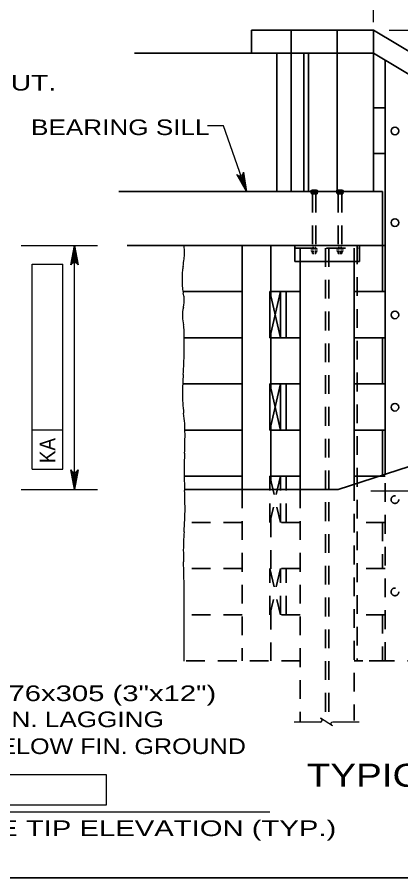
# Model space of a CAD drawing. Extents: x -6.4 to 73.1, y -66 to 0.
# Drawn here: x 48 to 50.94, y -21.25 to -14.64 of the extents above; entities that cross this region are included whole.
import ezdxf
from ezdxf.enums import TextEntityAlignment as Align

# ---------------------------------------------------------------- set-up
doc = ezdxf.new("R2010")
doc.units = 0
doc.header["$LTSCALE"] = 0.048
doc.header["$PDMODE"] = 32
doc.header["$PDSIZE"] = 0.024
doc.linetypes.add('MEDIUM_DASHED', pattern=[4.5, 3, -1.5])
for name, color, linetype, lineweight in [('1', 7, 'Continuous', 13), ('3', 7, 'Continuous', 35), ('4', 7, 'Continuous', 25), ('5', 7, 'Continuous', 25), ('8', 7, 'Continuous', 25)]:
    doc.layers.add(name, color=color, linetype=linetype, lineweight=lineweight)

msp = doc.modelspace()

# ---------------------------------------------------------------- hatches: boundary and pattern name
at = {"layer": '4'}
for points in [[(49.75758, -15.98183), (49.72792, -15.86708), (49.70933, -15.87358)], [(48.41525, -16.51333), (48.45467, -16.51333), (48.435, -16.39525)], [(48.41525, -18.14983), (48.45467, -18.14983), (48.435, -18.268)]]:
    msp.add_hatch(color=256, dxfattribs=at).paths.add_polyline_path(points)

# ---------------------------------------------------------------- linework, layer by layer
at = {"layer": '1', "lineweight": 35}
msp.add_lwpolyline([(35.75, -21.25), (67.25, -21.25), (67.25, -0.75), (35.75, -0.75)], close=True, dxfattribs=at)
at = {"layer": '3'}
for p, q in [((49.79517, -14.74175), (50.73183, -14.74175)), ((49.79517, -14.74175), (49.79517, -14.91892)), ((50.10025, -14.74175), (50.10025, -15.98183)), ((50.4525, -14.74175), (50.4525, -14.91892)), ((50.73183, -14.74175), (54.24875, -16.83867)), ((50.73183, -14.74175), (50.73183, -14.91892)), ((48.896, -14.91892), (50.73183, -14.91892)), ((49.99017, -14.91892), (49.99017, -15.98183)), ((50.1985, -14.91892), (50.1985, -15.98183)), ((50.23233, -14.91892), (50.23233, -15.98183)), ((50.4525, -14.91892), (50.4525, -15.98183)), ((50.73183, -14.91892), (54.24875, -17.01583)), ((50.73183, -14.91892), (50.73183, -15.98183)), ((50.8215, -18.15183), (50.8215, -14.97242)), ((50.8215, -15.33775), (50.73183, -15.33775)), ((50.8215, -15.68933), (50.73183, -15.68933)), ((48.77725, -15.98183), (50.80075, -15.98183)), ((50.25625, -15.99775), (50.25625, -15.98558)), ((50.294, -15.98183), (50.26158, -15.98183)), ((50.26733, -15.98558), (50.26733, -15.99775)), ((50.28867, -15.98558), (50.28867, -15.99775)), ((50.45408, -15.99775), (50.45408, -15.98558)), ((50.45908, -15.98183), (50.49142, -15.98183)), ((50.46442, -15.98558), (50.46442, -15.99775)), ((50.48575, -15.98558), (50.48575, -15.99775)), ((50.49675, -15.99775), (50.49675, -15.98558)), ((50.80075, -15.98183), (50.80075, -16.74958)), ((50.49675, -15.99775), (50.45408, -15.99775)), ((48.8395, -16.39525), (50.8215, -16.39525)), ((49.72392, -16.39525), (49.72392, -18.268)), ((49.944, -16.39525), (49.944, -16.78)), ((50.12892, -16.39525), (50.12892, -16.51825)), ((50.25583, -16.42667), (50.25583, -16.42133)), ((50.25583, -16.43967), (50.25583, -16.43342)), ((50.29358, -16.41758), (50.26117, -16.41758)), ((50.27225, -16.44342), (50.26117, -16.44342)), ((50.27333, -16.41033), (50.26442, -16.41033)), ((50.26442, -16.44342), (50.26442, -16.45625)), ((50.26692, -16.42133), (50.26692, -16.42667)), ((50.26692, -16.43342), (50.26692, -16.43967)), ((50.29067, -16.41033), (50.28233, -16.41033)), ((50.29358, -16.44342), (50.28275, -16.44342)), ((50.28825, -16.42133), (50.28825, -16.42667)), ((50.28825, -16.43342), (50.28825, -16.43967)), ((50.29067, -16.44342), (50.29067, -16.45625)), ((50.2985, -16.42667), (50.2985, -16.42133)), ((50.2985, -16.43967), (50.2985, -16.43342)), ((50.45442, -16.42725), (50.45442, -16.42133)), ((50.45442, -16.43967), (50.45442, -16.43333)), ((50.45942, -16.41758), (50.49175, -16.41758)), ((50.45942, -16.44342), (50.47175, -16.44342)), ((50.46225, -16.41033), (50.47175, -16.41033)), ((50.46225, -16.44342), (50.46225, -16.45625)), ((50.46475, -16.42133), (50.46475, -16.42725)), ((50.46475, -16.43333), (50.46475, -16.43967)), ((50.47775, -16.44342), (50.49175, -16.44342)), ((50.47892, -16.41033), (50.4885, -16.41033)), ((50.48608, -16.42133), (50.48608, -16.42725)), ((50.48608, -16.43333), (50.48608, -16.43967)), ((50.4885, -16.44342), (50.4885, -16.45625)), ((50.49708, -16.42725), (50.49708, -16.42133)), ((50.49708, -16.43967), (50.49708, -16.43333)), ((50.62408, -16.39525), (50.62408, -16.51825)), ((50.27392, -16.45625), (50.26442, -16.45625)), ((50.29067, -16.45625), (50.28117, -16.45625)), ((50.46225, -16.45625), (50.47175, -16.45625)), ((50.47775, -16.45625), (50.4885, -16.45625)), ((50.12892, -16.51825), (50.62408, -16.51825)), ((50.16992, -16.51825), (50.16992, -18.268)), ((50.58308, -16.51825), (50.58308, -18.21183)), ((49.72392, -16.74958), (49.26917, -16.74958)), ((49.93717, -17.10392), (49.93717, -16.74958)), ((49.93717, -16.74958), (50.01742, -17.10392)), ((50.01742, -16.74958), (49.93717, -17.10392)), ((50.16992, -16.74958), (49.93717, -16.74958)), ((50.01742, -17.10392), (50.01742, -16.74958)), ((50.06283, -17.10392), (50.06283, -16.74958)), ((50.16992, -16.74958), (50.12667, -16.74958)), ((50.8215, -16.74958), (50.58308, -16.74958)), ((49.72392, -17.10392), (49.27925, -17.10392)), ((50.16992, -17.10392), (49.93717, -17.10392)), ((49.944, -17.0735), (49.944, -17.48867)), ((54.09275, -17.09908), (50.46075, -18.268)), ((50.8215, -17.10392), (50.58308, -17.10392)), ((50.80075, -17.10392), (50.80075, -17.45825)), ((49.72392, -17.45825), (49.26717, -17.45825)), ((49.93717, -17.81258), (49.93717, -17.45825)), ((49.93717, -17.45825), (50.01742, -17.81258)), ((50.16992, -17.45825), (49.93717, -17.45825)), ((50.06283, -17.81258), (50.06283, -17.45825)), ((50.8215, -17.45825), (50.58308, -17.45825)), ((49.72392, -17.81258), (49.28442, -17.81258)), ((50.16992, -17.81258), (49.93717, -17.81258)), ((49.944, -17.78217), (49.944, -18.19733)), ((50.8215, -17.81258), (50.58308, -17.81258)), ((50.80075, -17.81258), (50.80075, -18.16692)), ((49.72392, -18.16692), (49.27875, -18.16692)), ((50.16992, -18.16692), (49.93717, -18.16692)), ((50.8215, -18.16692), (50.58308, -18.16692)), ((49.2815, -18.268), (50.46075, -18.268))]:
    msp.add_line(p, q, dxfattribs=at)
at = {"layer": '3', "linetype": 'MEDIUM_DASHED'}
for p, q in [((50.2645, -15.99775), (50.2645, -16.41758)), ((50.29075, -15.99775), (50.29075, -16.41758)), ((50.46233, -15.99775), (50.46233, -16.41758)), ((50.48858, -15.99775), (50.48858, -16.41758)), ((50.6075, -16.39525), (50.6075, -19.58425)), ((49.93717, -18.52125), (49.93717, -18.16692)), ((49.93717, -18.16692), (50.01742, -18.52125)), ((50.06283, -18.52125), (50.06283, -18.16692)), ((50.8215, -19.58425), (50.8215, -18.15183)), ((50.58308, -18.21183), (50.58308, -20.0425)), ((49.72392, -18.268), (49.72392, -19.58425)), ((50.16992, -18.268), (50.16992, -20.05342)), ((49.944, -18.49083), (49.944, -18.906)), ((49.72392, -18.52125), (49.28225, -18.52125)), ((50.16992, -18.52125), (49.93717, -18.52125)), ((50.8215, -18.52125), (50.58308, -18.52125)), ((50.80075, -18.52125), (50.80075, -18.87558)), ((49.72392, -18.87558), (49.27475, -18.87558)), ((49.93717, -19.22992), (49.93717, -18.87558)), ((49.93717, -18.87558), (50.01742, -19.22992)), ((50.01742, -18.87558), (49.93717, -19.22992)), ((50.16992, -18.87558), (49.93717, -18.87558)), ((50.01742, -19.22992), (50.01742, -18.87558)), ((50.06283, -19.22992), (50.06283, -18.87558)), ((50.8215, -18.87558), (50.58308, -18.87558)), ((49.944, -19.1995), (49.944, -19.58425)), ((49.72392, -19.22992), (49.27842, -19.22992)), ((50.16992, -19.22992), (49.93717, -19.22992)), ((50.8215, -19.22992), (50.58308, -19.22992)), ((50.80075, -19.22992), (50.80075, -19.58425)), ((50.16992, -19.58425), (49.27842, -19.58425)), ((51.87083, -19.58425), (50.58308, -19.58425)), ((50.69825, -19.58425), (50.87542, -19.58425))]:
    msp.add_line(p, q, dxfattribs=at)
at = {"layer": '3'}
for points in [[(50.25625, -15.99775), (50.29892, -15.99775), (50.29892, -15.98558)], [(50.01742, -17.81258), (50.01742, -17.45825), (49.93717, -17.81258)]]:
    msp.add_lwpolyline(points, dxfattribs=at)
at = {"layer": '3', "linetype": 'MEDIUM_DASHED'}
msp.add_lwpolyline([(50.01742, -18.52125), (50.01742, -18.16692), (49.93717, -18.52125)], dxfattribs=at)
at = {"layer": '3'}
for centre in [(50.89713, -15.51643), (50.89713, -16.22006), (50.89713, -16.92872), (50.89713, -17.63738)]:
    msp.add_circle(centre, 0.02953, dxfattribs=at)
at = {"layer": '3', "linetype": 'MEDIUM_DASHED'}
for centre in [(50.89713, -18.34604), (50.89713, -19.0547)]:
    msp.add_circle(centre, 0.02953, dxfattribs=at)
at = {"layer": '3'}
for centre, radius, start, end in [((50.26177, -15.98774), 0.00592, 88.17294, 158.71305), ((50.26177, -15.98774), 0.00592, 21.28694, 88.17294), ((50.27795, -15.99878), 0.01696, 51.05, 128.95), ((50.29375, -15.9872), 0.00539, 17.45181, 162.54819), ((50.45923, -15.9872), 0.00539, 17.45181, 162.54819), ((50.47503, -15.99878), 0.01696, 51.05, 128.95), ((50.49122, -15.98774), 0.00592, 91.82706, 158.71306), ((50.49122, -15.98774), 0.00592, 21.28694, 91.82706), ((50.2614, -16.42351), 0.00592, 88.17294, 158.71305), ((50.2614, -16.4375), 0.00592, 201.28694, 271.82706), ((50.2614, -16.42351), 0.00592, 21.28694, 88.17294), ((50.2614, -16.4375), 0.00592, 271.82706, 338.71306), ((50.27758, -16.43455), 0.01696, 51.05, 128.95), ((50.27758, -16.42646), 0.01696, 231.05, 256.0077), ((50.27758, -16.42646), 0.01696, 284.34274, 308.95), ((50.29339, -16.42298), 0.00539, 17.45181, 162.54819), ((50.29339, -16.43803), 0.00539, 197.45181, 342.54819), ((50.45962, -16.42298), 0.00539, 17.45181, 162.54819), ((50.45962, -16.43803), 0.00539, 197.45181, 342.54819), ((50.47542, -16.43455), 0.01696, 51.05, 128.95), ((50.47542, -16.42646), 0.01696, 231.05, 257.49177), ((50.47542, -16.42646), 0.01696, 277.88621, 308.95), ((50.4916, -16.42351), 0.00592, 91.82706, 158.71306), ((50.4916, -16.4375), 0.00592, 201.28694, 268.17294), ((50.4916, -16.42351), 0.00592, 21.28694, 91.82706), ((50.4916, -16.4375), 0.00592, 268.17294, 338.71305)]:
    msp.add_arc(centre, radius, start, end, dxfattribs=at)
at = {"layer": '3', "lineweight": 25}
for centre, radius, start, end in [((48.42474, -16.45944), 0.85604, 0, 4.30041), ((47.96951, -16.33175), 1.31933, 350.22511, 352.77729), ((48.97705, -16.45944), 0.30373, 352.77729, 0), ((49.6657, -16.62397), 0.40185, 170.22511, 174.85038), ((49.9781, -16.65213), 0.71552, 174.85038, 180), ((50.14143, -16.65213), 0.87884, 180, 184.64624), ((49.4982, -16.7044), 0.2335, 184.64624, 194.09577), ((49.02709, -16.8227), 0.25224, 5.00495, 14.09577), ((49.07832, -16.81821), 0.20082, 345.34471, 5.00496), ((49.49811, -16.92799), 0.23309, 165.34471, 183.58075), ((49.76231, -16.91146), 0.4978, 183.58075, 190.71943), ((48.975, -17.0605), 0.30349, 1.57285, 10.71943), ((47.04107, -17.1136), 2.23815, 0, 1.57285), ((42.58886, -17.1136), 6.69035, 359.0903, 0), ((46.28593, -17.17231), 2.99281, 355.92772, 359.0903), ((51.55928, -17.54774), 2.29388, 175.92772, 179.54026), ((50.40898, -17.53851), 1.14355, 179.54026, 187.19626), ((47.96778, -17.84675), 1.31704, 0.06302, 7.19626), ((46.30843, -17.84857), 2.97639, 357.26093, 0.06302), ((51.96358, -18.11912), 2.68522, 177.26093, 180.21106), ((52.99667, -18.11532), 3.71833, 180.21106, 182.50023), ((46.20283, -18.41197), 3.08199, 359.98578, 2.50023), ((47.00966, -18.41217), 2.27516, 355.43722, 359.98579), ((51.09012, -18.73781), 1.81827, 175.43722, 180.5256), ((52.82053, -18.72194), 3.54876, 180.5256, 181.65618), ((20.08141, -19.66855), 29.20404, 1.26207, 1.65618), ((46.29577, -19.09102), 2.98333, 0, 1.26207), ((-119.97358, -19.09102), 169.25267, 359.83244, 0)]:
    msp.add_arc(centre, radius, start, end, dxfattribs=at)
at = {"layer": '3'}
for p in [(50.26342, -15.982), (50.264, -15.982), (50.26467, -15.982), (50.26492, -15.98258), (50.26525, -15.982), (50.2655, -15.98258), (50.26583, -15.982), (50.26583, -15.98317), (50.26608, -15.98258), (50.26642, -15.982), (50.26642, -15.98317), (50.26667, -15.98258), (50.26675, -15.98375), (50.267, -15.982), (50.267, -15.98317), (50.267, -15.98433), (50.26725, -15.98258), (50.26725, -15.98375), (50.26725, -15.98492), (50.26758, -15.982), (50.26758, -15.98317), (50.26758, -15.98433), (50.26792, -15.98258), (50.26792, -15.98375), (50.26792, -15.98492), (50.26817, -15.982), (50.26817, -15.98317), (50.26817, -15.98433), (50.2685, -15.98258), (50.2685, -15.98375), (50.26875, -15.982), (50.26875, -15.98317), (50.26875, -15.98433), (50.26908, -15.98258), (50.26908, -15.98375), (50.26933, -15.982), (50.26933, -15.98317), (50.26967, -15.98258), (50.26967, -15.98375), (50.26992, -15.982), (50.26992, -15.98317), (50.27025, -15.98258), (50.2705, -15.982), (50.2705, -15.98317), (50.27083, -15.98258), (50.27108, -15.982), (50.27108, -15.98317), (50.27142, -15.98258), (50.27175, -15.982), (50.272, -15.98258), (50.27233, -15.982), (50.27258, -15.98258), (50.27292, -15.982), (50.2735, -15.982), (50.27408, -15.982), (50.27467, -15.982), (50.27525, -15.982), (50.28058, -15.982), (50.28117, -15.982), (50.28175, -15.982), (50.28233, -15.982), (50.28292, -15.982), (50.28325, -15.98258), (50.2835, -15.982), (50.28383, -15.98258), (50.28417, -15.982), (50.28442, -15.98258), (50.28467, -15.982), (50.28467, -15.98317), (50.285, -15.98258), (50.28533, -15.982), (50.28533, -15.98317), (50.28558, -15.98258), (50.28592, -15.982), (50.28592, -15.98317), (50.28617, -15.98258), (50.28617, -15.98375), (50.2865, -15.982), (50.2865, -15.98317), (50.28675, -15.98258), (50.28675, -15.98375), (50.28708, -15.982), (50.28708, -15.98317), (50.28708, -15.98433), (50.28733, -15.98258), (50.28733, -15.98375), (50.28767, -15.982), (50.28767, -15.98317), (50.28767, -15.98433), (50.28792, -15.98258), (50.28792, -15.98375), (50.28792, -15.98492), (50.28825, -15.982), (50.28825, -15.98317), (50.28825, -15.98433), (50.2885, -15.98258), (50.2885, -15.98375), (50.2885, -15.98492), (50.28867, -15.98258), (50.28867, -15.98375), (50.28867, -15.98492), (50.28892, -15.982), (50.28892, -15.98317), (50.28892, -15.98433), (50.28925, -15.98258), (50.28925, -15.98375), (50.2895, -15.982), (50.2895, -15.98317), (50.28983, -15.98258), (50.29017, -15.982), (50.29017, -15.98317), (50.29042, -15.98258), (50.29067, -15.982), (50.291, -15.98258), (50.29133, -15.982), (50.29192, -15.982), (50.2925, -15.982), (50.4605, -15.982), (50.46108, -15.982), (50.46175, -15.982), (50.462, -15.98258), (50.46233, -15.982), (50.46258, -15.98258), (50.46292, -15.982), (50.46292, -15.98317), (50.46317, -15.98258), (50.4635, -15.982), (50.4635, -15.98317), (50.46375, -15.98258), (50.46383, -15.98375), (50.46408, -15.982), (50.46408, -15.98317), (50.46408, -15.98433), (50.46433, -15.98258), (50.46433, -15.98375), (50.46433, -15.98492), (50.4645, -15.98258), (50.4645, -15.98375), (50.4645, -15.98492), (50.46475, -15.982), (50.46475, -15.98317), (50.46475, -15.98433), (50.46508, -15.98258), (50.46508, -15.98375), (50.46508, -15.98492), (50.46533, -15.982), (50.46533, -15.98317), (50.46533, -15.98433), (50.46567, -15.98258), (50.46567, -15.98375), (50.46592, -15.982), (50.46592, -15.98317), (50.46592, -15.98433), (50.46625, -15.98258), (50.46625, -15.98375), (50.4665, -15.982), (50.4665, -15.98317), (50.46683, -15.98258), (50.46683, -15.98375), (50.46708, -15.982), (50.46708, -15.98317), (50.46742, -15.98258), (50.46775, -15.982), (50.46775, -15.98317), (50.468, -15.98258), (50.46833, -15.982), (50.46833, -15.98317), (50.46858, -15.98258), (50.46892, -15.982), (50.46917, -15.98258), (50.4695, -15.982), (50.46983, -15.98258), (50.47008, -15.982), (50.47067, -15.982), (50.47125, -15.982), (50.47183, -15.982), (50.47242, -15.982), (50.47775, -15.982), (50.47833, -15.982), (50.47892, -15.982), (50.4795, -15.982), (50.48017, -15.982), (50.48042, -15.98258), (50.48067, -15.982), (50.481, -15.98258), (50.48133, -15.982), (50.48158, -15.98258), (50.48192, -15.982), (50.48192, -15.98317), (50.48217, -15.98258), (50.4825, -15.982), (50.4825, -15.98317), (50.48275, -15.98258), (50.48308, -15.982), (50.48308, -15.98317), (50.48333, -15.98258), (50.48333, -15.98375), (50.48367, -15.982), (50.48367, -15.98317), (50.484, -15.98258), (50.484, -15.98375), (50.48425, -15.982), (50.48425, -15.98317), (50.48425, -15.98433), (50.4845, -15.98258), (50.4845, -15.98375), (50.48483, -15.982), (50.48483, -15.98317), (50.48483, -15.98433), (50.48517, -15.98258), (50.48517, -15.98375), (50.48517, -15.98492), (50.48542, -15.982), (50.48542, -15.98317), (50.48542, -15.98433), (50.48575, -15.98258), (50.48575, -15.98375), (50.48575, -15.98492), (50.486, -15.982), (50.486, -15.98317), (50.486, -15.98433), (50.48633, -15.98258), (50.48633, -15.98375), (50.48658, -15.982), (50.48658, -15.98317), (50.48692, -15.98258), (50.48725, -15.982), (50.48725, -15.98317), (50.4875, -15.98258), (50.48775, -15.982), (50.48808, -15.98258), (50.48842, -15.982), (50.489, -15.982), (50.48958, -15.982)]:
    msp.add_point(p, dxfattribs=at)
at = {"layer": '4'}
for p, q in [((50.73183, -14.68017), (50.73183, -12.92633)), ((50.85358, -14.74175), (51.09342, -14.74175)), ((48.0265, -16.39525), (48.61217, -16.39525)), ((48.435, -18.268), (48.435, -16.39525)), ((48.11008, -18.113), (48.11008, -16.53817)), ((48.11008, -16.53817), (48.34625, -16.53817)), ((48.34625, -18.113), (48.34625, -16.53817)), ((48.11008, -17.8105), (48.34625, -17.8105)), ((48.11008, -18.113), (48.34625, -18.113)), ((48.0265, -18.268), (48.61217, -18.268)), ((54.53475, -18.28233), (50.71167, -18.28233)), ((47.03017, -20.45633), (48.6785, -20.45633)), ((48.6785, -20.45633), (48.6785, -20.69258)), ((46.98075, -20.74267), (49.93708, -20.74267)), ((48.6785, -20.69258), (47.03017, -20.69258))]:
    msp.add_line(p, q, dxfattribs=at)
at = {"layer": '4', "lineweight": 35}
msp.add_line((50.8215, -15.67592), (50.8215, -17.55908), dxfattribs=at)
at = {"layer": '4'}
for points in [[(49.75758, -15.98183), (49.58142, -15.477), (49.45633, -15.477)], [(49.75758, -15.98183), (49.68208, -15.85025), (49.69333, -15.8585), (49.70475, -15.86075), (49.71475, -15.85908), (49.72367, -15.85417), (49.73108, -15.84525), (49.73483, -15.83183), (49.75758, -15.98183), (49.73108, -15.84525), (49.72367, -15.85417), (49.75758, -15.98183), (49.71475, -15.85908), (49.70475, -15.86075), (49.75758, -15.98183), (49.69333, -15.8585)], [(48.435, -16.39525), (48.463, -16.54442), (48.455, -16.53292), (48.445, -16.527), (48.435, -16.52525), (48.425, -16.527), (48.415, -16.53292), (48.407, -16.54442), (48.435, -16.39525), (48.415, -16.53292), (48.425, -16.527), (48.435, -16.39525), (48.435, -16.52525), (48.445, -16.527), (48.435, -16.39525), (48.455, -16.53292)], [(48.435, -18.268), (48.407, -18.11883), (48.415, -18.13033), (48.425, -18.13625), (48.435, -18.138), (48.445, -18.13625), (48.455, -18.13033), (48.463, -18.11883), (48.435, -18.268), (48.455, -18.13033), (48.445, -18.13625), (48.435, -18.268), (48.435, -18.138), (48.425, -18.13625), (48.435, -18.268), (48.415, -18.13033)]]:
    msp.add_lwpolyline(points, dxfattribs=at)
for points in [[(49.75758, -15.98183), (49.72792, -15.86708), (49.70933, -15.87358)], [(48.41525, -16.51333), (48.45467, -16.51333), (48.435, -16.39525)], [(48.41525, -18.14983), (48.45467, -18.14983), (48.435, -18.268)]]:
    msp.add_lwpolyline(points, close=True, dxfattribs=at)
at = {"layer": '8', "linetype": 'MEDIUM_DASHED', "lineweight": 35}
for p, q in [((50.12892, -16.41492), (50.62408, -16.41492)), ((50.16992, -16.41492), (50.16992, -16.51825)), ((50.36475, -16.41492), (50.36475, -20.04942)), ((50.38842, -16.41492), (50.38842, -20.06425)), ((50.58308, -16.41492), (50.58308, -16.51825))]:
    msp.add_line(p, q, dxfattribs=at)
at = {"layer": '8'}
for p, q in [((50.32608, -20.05408), (50.12217, -20.05408)), ((50.62342, -20.05408), (50.41933, -20.05408))]:
    msp.add_line(p, q, dxfattribs=at)
msp.add_lwpolyline([(50.4125, -20.0795), (50.41833, -20.08308), (50.32592, -20.025), (50.33208, -20.02892)], dxfattribs=at)
for centre, start, end in [((50.32482, -20.04046), 275.32859, 57.86724), ((50.41932, -20.06768), 90, 240)]:
    msp.add_arc(centre, 0.01364, start, end, dxfattribs=at)

# ---------------------------------------------------------------- texts
at = {"layer": '4'}
for s, width, p in [('BEARING SILL', 1.25, (48.10183, -15.54783)), ('BELOW FIN. GROUND', 1.2, (47.73042, -20.29983)), ('ABUT. PILE TIP ELEVATION (TYP.)', 1.4, (46.78883, -20.9295))]:
    msp.add_text(s, height=0.12, dxfattribs=dict(at, width=width)).set_placement(p)
at = {"layer": '4', "width": 0.9}
msp.add_text('KA', height=0.12, rotation=90, dxfattribs=at).set_placement((48.28817, -17.96975), align=Align.CENTER)
at = {"layer": '4', "width": 1.25}
msp.add_text('TYPICAL WING ELEVATION', height=0.1772, dxfattribs=at).set_placement((52.15417, -20.55142), align=Align.CENTER)
at = {"layer": '5'}
for s, width, p in [('76x305 (3"x12") TIMBER LAGGING ABUT.', 1.35, (44.13217, -15.20583)), ('3-76x305 (3"x12")', 1.4, (47.72892, -19.8935)), ('MIN. LAGGING', 1.25, (47.72892, -20.0935))]:
    msp.add_text(s, height=0.12, dxfattribs=dict(at, width=width)).set_placement(p)

doc.saveas('drawing.dxf')
